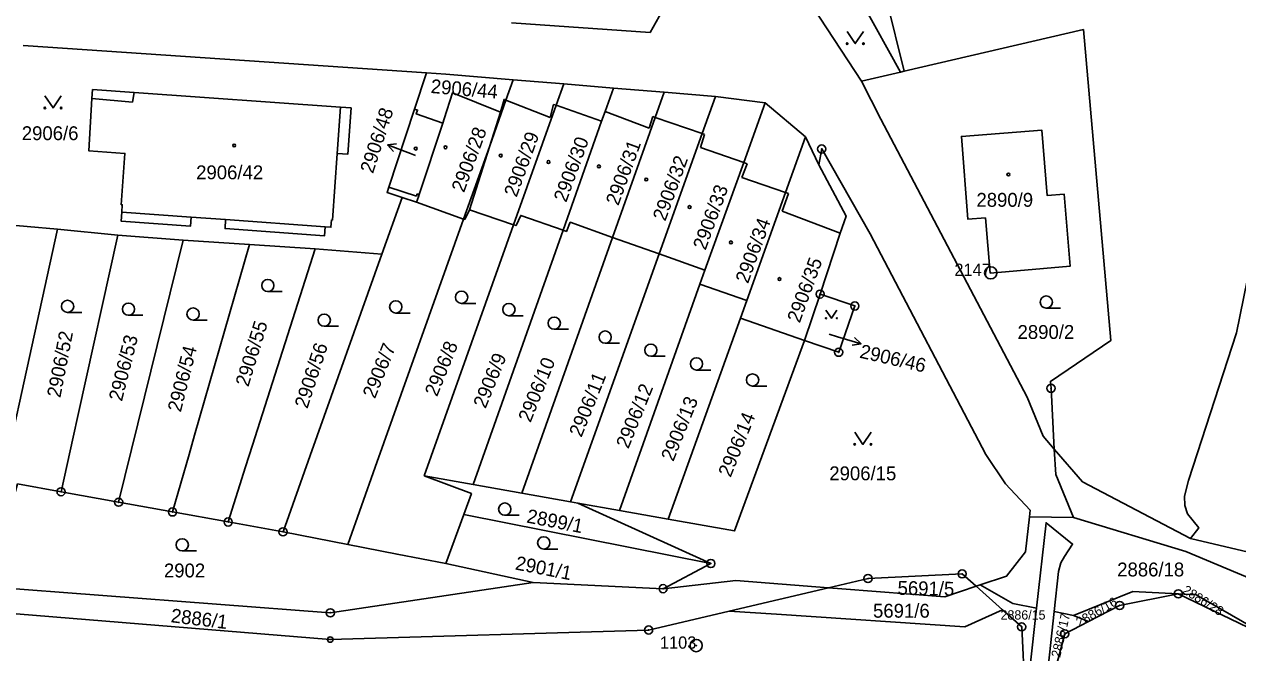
# Model space of a CAD drawing. Extents: x -644096 to -634268, y -1141430 to -1133463.
# Drawn here: x -640028.5 to -639879.7, y -1138359.5 to -1138282.4 of the extents above; entities that cross this region are included whole.
import ezdxf

# ---------------------------------------------------------------- set-up
doc = ezdxf.new("R2010")
doc.units = 0
for name, color, linetype in [('_CIVIL_CONSTRUCTION', 7, 'Continuous'), ('M_Svah_Nasyp', 7, 'Continuous'), ('M_Svah_Zarez', 7, 'Continuous'), ('spodek_zarez', 7, 'Continuous'), ('svrsek_osa_sjezdy', 7, 'Continuous'), ('svrsek_osa_VRT', 7, 'Continuous'), ('svrsek_popisy_VRT', 7, 'Continuous'), ('terminal_VRT', 7, 'Continuous')]:
    doc.layers.add(name, color=color, linetype=linetype)

msp = doc.modelspace()

# ---------------------------------------------------------------- linework, layer by layer
at = {"layer": '_CIVIL_CONSTRUCTION'}
for centre, radius in [((-639930.73, -1138297.73), 0.5), ((-639930.73, -1138297.73), 0.0303), ((-639910.01, -1138312.92), 0.75), ((-639910.01, -1138312.92), 0.03), ((-639930.93, -1138315.53), 0.5), ((-639930.93, -1138315.53), 0.0303), ((-639926.67, -1138316.98), 0.5), ((-639926.67, -1138316.98), 0.0303), ((-639928.65, -1138322.66), 0.5), ((-639928.65, -1138322.66), 0.0303), ((-639902.61, -1138327.08), 0.5), ((-639902.61, -1138327.08), 0.0303), ((-640024, -1138339.77), 0.5), ((-640024, -1138339.77), 0.0303), ((-640016.94, -1138341.05), 0.5), ((-640016.94, -1138341.05), 0.0303), ((-640010.34, -1138342.24), 0.5), ((-640010.34, -1138342.24), 0.0303), ((-640003.51, -1138343.47), 0.5), ((-640003.51, -1138343.47), 0.0303), ((-639996.78, -1138344.68), 0.5), ((-639996.78, -1138344.68), 0.0303), ((-639944.33, -1138348.56), 0.5), ((-639944.33, -1138348.56), 0.0303), ((-639913.51, -1138349.84), 0.5), ((-639950.18, -1138351.66), 0.5), ((-639925.05, -1138350.41), 0.5), ((-639925.05, -1138350.41), 0.0303), ((-639913.51, -1138349.84), 0.0303), ((-639950.18, -1138351.66), 0.0303), ((-639887.01, -1138352.29), 0.5), ((-639887.01, -1138352.29), 0.0303), ((-639990.99, -1138354.61), 0.5), ((-639894.2, -1138353.71), 0.5), ((-639894.2, -1138353.71), 0.0303), ((-639990.99, -1138354.61), 0.0303), ((-639951.96, -1138356.72), 0.5), ((-639951.96, -1138356.72), 0.0303), ((-639906.21, -1138356.34), 0.5), ((-639906.21, -1138356.34), 0.0303), ((-639900.93, -1138357.19), 0.5), ((-639900.93, -1138357.19), 0.0303), ((-639991, -1138357.89), 0.335), ((-639991, -1138357.89), 0.0203), ((-639946.12, -1138358.63), 0.75), ((-639946.12, -1138358.63), 0.03)]:
    msp.add_circle(centre, radius, dxfattribs=at)
at = {"layer": 'M_Svah_Nasyp'}
for p, q in [((-640015.24, -1138291.99), (-640020.21, -1138291.55)), ((-640015.24, -1138291.99), (-640015.04, -1138290.8)), ((-639964.01, -1138293.86), (-639969.45, -1138291.75)), ((-639990.14, -1138298.27), (-639989.73, -1138292.59)), ((-639971.48, -1138297.47), (-639970.13, -1138293.22)), ((-639963.64, -1138292.26), (-639964.01, -1138293.86)), ((-639963.31, -1138292.38), (-639963.64, -1138292.26)), ((-639957.72, -1138294.34), (-639963.31, -1138292.38)), ((-639957.29, -1138293.13), (-639951.87, -1138295.19)), ((-639951.44, -1138293.77), (-639951.87, -1138295.19)), ((-639951.14, -1138293.87), (-639951.44, -1138293.77)), ((-639945.37, -1138295.85), (-639951.14, -1138293.87)), ((-639945.59, -1138297.55), (-639945.09, -1138295.95)), ((-639945.09, -1138295.95), (-639945.37, -1138295.85)), ((-639971.48, -1138297.47), (-639973.94, -1138305.19)), ((-639940.29, -1138299.41), (-639945.59, -1138297.55)), ((-639940.52, -1138301.24), (-639939.88, -1138299.55)), ((-639939.88, -1138299.55), (-639940.29, -1138299.41)), ((-639935.17, -1138303.08), (-639940.52, -1138301.24)), ((-639983.81, -1138302.4), (-639980.43, -1138303.51)), ((-639980.43, -1138303.51), (-639980.33, -1138303.25)), ((-639980.33, -1138303.25), (-639980.08, -1138303.33)), ((-639935.58, -1138305.35), (-639934.8, -1138303.21)), ((-639934.8, -1138303.21), (-639935.17, -1138303.08)), ((-640008.05, -1138306.09), (-640016.56, -1138305.48)), ((-639991.62, -1138307.28), (-640003.82, -1138306.4)), ((-639928.45, -1138308.06), (-639935.58, -1138305.35))]:
    msp.add_line(p, q, dxfattribs=at)
at = {"layer": 'M_Svah_Zarez'}
for centre in [(-640002.77, -1138297.3), (-639980.52, -1138297.69), (-639976.87, -1138297.53), (-639970.09, -1138298.55), (-639964.24, -1138299.33), (-639958.05, -1138299.87), (-639952.24, -1138301.48), (-639907.84, -1138300.87), (-639946.93, -1138304.85), (-639941.86, -1138309.19), (-639935.91, -1138313.68)]:
    msp.add_circle(centre, 0.175, dxfattribs=at)
at = {"layer": 'spodek_zarez'}
msp.add_circle((-638683.07, -1137056.85), 1378.08, dxfattribs=at)
at = {"layer": 'svrsek_osa_sjezdy'}
for p, q in [((-639998.65, -1138315.23), (-639996.9, -1138315.23)), ((-639974.89, -1138316.67), (-639973.14, -1138316.67)), ((-640023.2, -1138317.78), (-640021.45, -1138317.78)), ((-640015.74, -1138318.13), (-640013.99, -1138318.13)), ((-639982.96, -1138317.85), (-639981.21, -1138317.85)), ((-639969.09, -1138318.18), (-639967.34, -1138318.18)), ((-639903.19, -1138317.25), (-639901.44, -1138317.25)), ((-640007.82, -1138318.72), (-640006.07, -1138318.72)), ((-639991.73, -1138319.48), (-639989.98, -1138319.48)), ((-639963.53, -1138319.84), (-639961.78, -1138319.84)), ((-639957.28, -1138321.55), (-639955.53, -1138321.55)), ((-639951.68, -1138323.16), (-639949.93, -1138323.16)), ((-639946.09, -1138324.84), (-639944.34, -1138324.84)), ((-639939.21, -1138326.81), (-639937.46, -1138326.81)), ((-639969.6, -1138342.64), (-639967.85, -1138342.64)), ((-639964.82, -1138346.79), (-639963.07, -1138346.79)), ((-640009.14, -1138347.03), (-640007.39, -1138347.03))]:
    msp.add_line(p, q, dxfattribs=at)
for points in [[(-639927.61, -1138283.31), (-639926.61, -1138284.81), (-639925.61, -1138283.31)], [(-640025.99, -1138291.2), (-640024.99, -1138292.7), (-640023.99, -1138291.2)], [(-639930.21, -1138317.48), (-639929.54, -1138318.49), (-639928.87, -1138317.48)], [(-639926.68, -1138332.46), (-639925.68, -1138333.96), (-639924.68, -1138332.46)]]:
    msp.add_lwpolyline(points, dxfattribs=at)
for centre, radius in [((-639927.61, -1138284.81), 0.1), ((-639925.61, -1138284.81), 0.1), ((-640025.99, -1138292.7), 0.1), ((-640023.99, -1138292.7), 0.1), ((-639998.65, -1138314.48), 0.75), ((-639974.89, -1138315.92), 0.75), ((-640023.2, -1138317.03), 0.75), ((-640015.74, -1138317.38), 0.75), ((-639982.96, -1138317.1), 0.75), ((-639969.09, -1138317.43), 0.75), ((-639903.19, -1138316.5), 0.75), ((-640007.82, -1138317.97), 0.75), ((-639991.73, -1138318.73), 0.75), ((-639963.53, -1138319.09), 0.75), ((-639930.21, -1138318.49), 0.067), ((-639928.87, -1138318.49), 0.067), ((-639957.28, -1138320.8), 0.75), ((-639951.68, -1138322.41), 0.75), ((-639946.09, -1138324.09), 0.75), ((-639939.21, -1138326.06), 0.75), ((-639926.68, -1138333.96), 0.1), ((-639924.68, -1138333.96), 0.1), ((-639969.6, -1138341.89), 0.75), ((-639964.82, -1138346.04), 0.75), ((-640009.14, -1138346.28), 0.75)]:
    msp.add_circle(centre, radius, dxfattribs=at)
at = {"layer": 'svrsek_popisy_VRT'}
for p, q in [((-639983.97, -1138297.21), (-639982.86, -1138297.1)), ((-639981.17, -1138298.28), (-639983.97, -1138297.21)), ((-639983.97, -1138297.21), (-639983.22, -1138298.03)), ((-639980.54, -1138298.52), (-639981.17, -1138298.28)), ((-639929.82, -1138320.43), (-639928.78, -1138320.75)), ((-639928.78, -1138320.75), (-639925.91, -1138321.63)), ((-639925.91, -1138321.63), (-639926.72, -1138320.86)), ((-639925.91, -1138321.63), (-639927.01, -1138321.81))]:
    msp.add_line(p, q, dxfattribs=at)
at = {"layer": 'terminal_VRT'}
for p, q in [((-639937.78, -1138271.21), (-639925.86, -1138289.42)), ((-639979.21, -1138288.39), (-640028.65, -1138285.04)), ((-639980.67, -1138292.84), (-639979.21, -1138288.39)), ((-639921.06, -1138288.3), (-639925.86, -1138289.42)), ((-639921.06, -1138288.3), (-639920.64, -1138288.21)), ((-639968.55, -1138289.24), (-639969.45, -1138291.75)), ((-639962.37, -1138289.75), (-639968.55, -1138289.24)), ((-639956.28, -1138290.26), (-639962.37, -1138289.75)), ((-639950.04, -1138290.77), (-639956.28, -1138290.26)), ((-639943.74, -1138291.3), (-639950.04, -1138290.77)), ((-639937.67, -1138292.09), (-639943.74, -1138291.3)), ((-639932.71, -1138296.24), (-639937.67, -1138292.09)), ((-639931.08, -1138299.69), (-639932.71, -1138296.24)), ((-639984.67, -1138310.64), (-639982.19, -1138303.67)), ((-639980.4, -1138304.27), (-639982.19, -1138303.67)), ((-639974.64, -1138306.33), (-639980.4, -1138304.27)), ((-640032.63, -1138306.87), (-640024.43, -1138307.56)), ((-640024.43, -1138307.56), (-640017.05, -1138308.31)), ((-639979.48, -1138337.8), (-639968.52, -1138307.02)), ((-639973.48, -1138338.87), (-639962.45, -1138307.69)), ((-640017.05, -1138308.31), (-640009.02, -1138308.92)), ((-640016.94, -1138341.05), (-640009.02, -1138308.92)), ((-640009.02, -1138308.92), (-640000.89, -1138309.44)), ((-640000.89, -1138309.44), (-639992.84, -1138309.96)), ((-639967.51, -1138339.93), (-639956.37, -1138308.57)), ((-639950.65, -1138310.6), (-639956.37, -1138308.57)), ((-639992.84, -1138309.96), (-639984.67, -1138310.64)), ((-639961.53, -1138340.99), (-639950.65, -1138310.6)), ((-639945.07, -1138312.58), (-639950.65, -1138310.6)), ((-639945.69, -1138314.31), (-639945.07, -1138312.58)), ((-639955.54, -1138342.06), (-639945.69, -1138314.31)), ((-639939.92, -1138316.33), (-639945.69, -1138314.31)), ((-639932.86, -1138321.2), (-639930.93, -1138315.53)), ((-639940.69, -1138318.48), (-639939.92, -1138316.33)), ((-639949.54, -1138343.13), (-639940.69, -1138318.48)), ((-639932.86, -1138321.2), (-639940.69, -1138318.48)), ((-639973.48, -1138338.87), (-639979.48, -1138337.8)), ((-639967.51, -1138339.93), (-639973.48, -1138338.87)), ((-640016.94, -1138341.05), (-640024, -1138339.77)), ((-639961.53, -1138340.99), (-639967.51, -1138339.93)), ((-640010.34, -1138342.24), (-640016.94, -1138341.05)), ((-640003.51, -1138343.47), (-640010.34, -1138342.24)), ((-639960.65, -1138341.15), (-639961.53, -1138340.99)), ((-639944.33, -1138348.56), (-639960.65, -1138341.15)), ((-639960.65, -1138341.15), (-639955.54, -1138342.06)), ((-639955.54, -1138342.06), (-639949.54, -1138343.13)), ((-639996.78, -1138344.68), (-640003.51, -1138343.47)), ((-639974.61, -1138342.54), (-639976.82, -1138348.57)), ((-639974.61, -1138342.54), (-639944.33, -1138348.56)), ((-639905.27, -1138342.83), (-639899.84, -1138342.91)), ((-639988.82, -1138346.25), (-639996.78, -1138344.68)), ((-639885.53, -1138345.48), (-639875.02, -1138347.98)), ((-639976.82, -1138348.57), (-639966.11, -1138350.91)), ((-639950.18, -1138351.66), (-639944.33, -1138348.56)), ((-639950.18, -1138351.66), (-639966.11, -1138350.91)), ((-639911.8, -1138351.36), (-639911.31, -1138351.2)), ((-639942.08, -1138354.4), (-639929.89, -1138351.54)), ((-639908.57, -1138354.24), (-639911.8, -1138351.36)), ((-639887.01, -1138352.29), (-639874.8, -1138358.19)), ((-639899.86, -1138354.95), (-639902.22, -1138354.47)), ((-639899.86, -1138354.95), (-639898, -1138355.67))]:
    msp.add_line(p, q, dxfattribs=at)
for points in [[(-639968.76, -1138282.27), (-639951.78, -1138283.45), (-639945.53, -1138272.31), (-639954.38, -1138257.06)], [(-639927.88, -1138269.33), (-639925.7, -1138279.99), (-639921.06, -1138288.3)], [(-639920.64, -1138288.21), (-639922.77, -1138279.39), (-639923.21, -1138275.47)], [(-639920.64, -1138288.21), (-639898.65, -1138283.1), (-639895.28, -1138321.22), (-639902.68, -1138326.23), (-639902.61, -1138327.08), (-639902.21, -1138334.54)], [(-639885.53, -1138345.48), (-639884.5, -1138344.2), (-639885.86, -1138342.47), (-639886.21, -1138341.46), (-639886.26, -1138340.32), (-639885.76, -1138338.38), (-639879.87, -1138320.28), (-639872.27, -1138282.97)], [(-639968.55, -1138289.24), (-639976.81, -1138288.55), (-639979.21, -1138288.39)], [(-639968.52, -1138307.02), (-639963.31, -1138292.38), (-639962.37, -1138289.75)], [(-639962.45, -1138307.69), (-639957.72, -1138294.34), (-639957.29, -1138293.13), (-639956.28, -1138290.26)], [(-639925.86, -1138289.42), (-639923.47, -1138294.06), (-639905.52, -1138328.16), (-639903.59, -1138332.94), (-639902.21, -1138334.54)], [(-639988.43, -1138292.68), (-639988.84, -1138298.37), (-639990.14, -1138298.27), (-639990.73, -1138306.45), (-639990.85, -1138306.44), (-639990.92, -1138307.33), (-639991.62, -1138307.28), (-639991.7, -1138308.37), (-640003.9, -1138307.49), (-640003.82, -1138306.4), (-640008.05, -1138306.09), (-640008.13, -1138307.19), (-640016.64, -1138306.57), (-640016.56, -1138305.48), (-640016.5, -1138304.58), (-640016.63, -1138304.57), (-640016.17, -1138298.28), (-640020.61, -1138297.96), (-640020.21, -1138291.55), (-640020.14, -1138290.44), (-640015.04, -1138290.8), (-639989.73, -1138292.59), (-639988.43, -1138292.68)], [(-639969.45, -1138291.75), (-639969.68, -1138291.66), (-639970.13, -1138293.22), (-639976, -1138290.84), (-639977.04, -1138294.03), (-639977.21, -1138294.55)], [(-639974.64, -1138306.33), (-639971.48, -1138297.47), (-639969.45, -1138291.75)], [(-639956.37, -1138308.57), (-639951.14, -1138293.87), (-639950.04, -1138290.77)], [(-639950.65, -1138310.6), (-639945.37, -1138295.85), (-639943.74, -1138291.3)], [(-639982.19, -1138303.67), (-639984.02, -1138303.07), (-639983.81, -1138302.4), (-639980.67, -1138292.84)], [(-639980.67, -1138292.84), (-639980.29, -1138292.97), (-639980.44, -1138293.43), (-639977.21, -1138294.55)], [(-639945.07, -1138312.58), (-639940.29, -1138299.41), (-639937.67, -1138292.09)], [(-639977.21, -1138294.55), (-639980.08, -1138303.33), (-639980.17, -1138303.59), (-639980.4, -1138304.27)], [(-639910.66, -1138306.17), (-639912.83, -1138306.32), (-639913.61, -1138296.19), (-639903.72, -1138295.43), (-639903.1, -1138303.42), (-639901.02, -1138303.26), (-639900.26, -1138312.1), (-639910.06, -1138312.96), (-639910.66, -1138306.17)], [(-639939.92, -1138316.33), (-639935.17, -1138303.08), (-639932.71, -1138296.24)], [(-639905.27, -1138342.83), (-639905.18, -1138342.03), (-639908.18, -1138338.79), (-639910.59, -1138335.19), (-639924.77, -1138308.15), (-639930.73, -1138297.73), (-639931.08, -1138299.69)], [(-639931.08, -1138299.69), (-639927.74, -1138305.98), (-639928.45, -1138308.06), (-639930.93, -1138315.53)], [(-639988.82, -1138346.25), (-639985.48, -1138336.74), (-639974.64, -1138306.33)], [(-639968.52, -1138307.02), (-639973.94, -1138305.19), (-639974.5, -1138306.38), (-639974.64, -1138306.33)], [(-639962.45, -1138307.69), (-639967.64, -1138305.88), (-639968.2, -1138307.13), (-639968.52, -1138307.02)], [(-640031.21, -1138338.46), (-640030, -1138332.96), (-640029.14, -1138329.03), (-640024.43, -1138307.56)], [(-639956.37, -1138308.57), (-639961.57, -1138306.72), (-639962.03, -1138307.84), (-639962.45, -1138307.69)], [(-640024, -1138339.77), (-640022.52, -1138333.06), (-640021.91, -1138330.3), (-640017.05, -1138308.31)], [(-640010.34, -1138342.24), (-640008.31, -1138335.2), (-640007.63, -1138332.82), (-640000.89, -1138309.44)], [(-640003.51, -1138343.47), (-640001.37, -1138336.73), (-640000.52, -1138334.07), (-639992.84, -1138309.96)], [(-639984.67, -1138310.64), (-639993.45, -1138335.32), (-639996.78, -1138344.68)], [(-639930.93, -1138315.53), (-639926.67, -1138316.98), (-639928.65, -1138322.66), (-639932.86, -1138321.2)], [(-639949.54, -1138343.13), (-639941.42, -1138344.57), (-639932.86, -1138321.2)], [(-639902.21, -1138334.54), (-639898.74, -1138338.57), (-639885.53, -1138345.48)], [(-639899.84, -1138342.91), (-639902.04, -1138337.66), (-639902.21, -1138334.54)], [(-639979.48, -1138337.8), (-639973.68, -1138340), (-639974.61, -1138342.54)], [(-640024, -1138339.77), (-640029.34, -1138338.81), (-640032.65, -1138350.73)], [(-639911.31, -1138351.2), (-639908.07, -1138350.13), (-639905.74, -1138347.12), (-639905.27, -1138342.83)], [(-639902.22, -1138354.47), (-639901.68, -1138349.54), (-639901.4, -1138348.48), (-639900.97, -1138347.7), (-639899.96, -1138346.18), (-639903.22, -1138343.57), (-639904.38, -1138354.04)], [(-639899.84, -1138342.91), (-639886.09, -1138347.1), (-639872.94, -1138352.6), (-639845.94, -1138357.86)], [(-639976.82, -1138348.57), (-639982.81, -1138347.43), (-639988.82, -1138346.25)], [(-639966.11, -1138350.91), (-639990.99, -1138354.61), (-640032.85, -1138351.44)], [(-639929.89, -1138351.54), (-639941.26, -1138350.67), (-639950.18, -1138351.66)], [(-639929.89, -1138351.54), (-639925.05, -1138350.41), (-639913.51, -1138349.84), (-639911.8, -1138351.36)], [(-639904.38, -1138354.04), (-639907.29, -1138353.45), (-639911.31, -1138351.2)], [(-639929.89, -1138351.54), (-639928.27, -1138351.67), (-639915.65, -1138352.64), (-639911.8, -1138351.36)], [(-639887.01, -1138352.29), (-639892.6, -1138351.98), (-639899.86, -1138354.95)], [(-639898, -1138355.67), (-639894.2, -1138353.71), (-639887.01, -1138352.29)], [(-639887.01, -1138352.29), (-639884.83, -1138352.4), (-639874.8, -1138358.19)], [(-639908.57, -1138354.24), (-639913.2, -1138356.32), (-639936.27, -1138354.79), (-639942.08, -1138354.4)], [(-639905.83, -1138364.11), (-639906.21, -1138356.34), (-639908.57, -1138354.24)], [(-639904.38, -1138354.04), (-639905.5, -1138364.15), (-639905.83, -1138364.11)], [(-640033.56, -1138354.39), (-639991, -1138357.89), (-639951.96, -1138356.72), (-639942.08, -1138354.4)], [(-639902.84, -1138364.38), (-639903.08, -1138362.43), (-639902.22, -1138354.47)], [(-639902.84, -1138364.38), (-639900.93, -1138357.19), (-639898, -1138355.67)]]:
    msp.add_lwpolyline(points, dxfattribs=at)

# ---------------------------------------------------------------- texts
at = {"layer": '_CIVIL_CONSTRUCTION'}
for s, p in [('2147', (-639914.46, -1138313.29)), ('1103', (-639950.57, -1138359.01))]:
    msp.add_text(s, height=1.5, dxfattribs=at).set_placement(p)
at = {"layer": 'svrsek_osa_VRT'}
for s, height, rotation, p in [('2906/44', 1.7, 355, (-639978.72, -1138290.86)), ('2906/48', 1.7, 72, (-639985.76, -1138300.83)), ('2906/28', 1.7, 70, (-639974.59, -1138303.16)), ('2906/29', 1.7, 70, (-639968.15, -1138303.74)), ('2906/30', 1.7, 70, (-639962.06, -1138304.36)), ('2906/31', 1.7, 70, (-639955.67, -1138304.77)), ('2906/32', 1.7, 70, (-639949.91, -1138306.67)), ('2906/33', 1.7, 70, (-639944.98, -1138310.23)), ('2906/34', 1.7, 70, (-639939.77, -1138314.32)), ('2906/35', 1.7, 70, (-639933.43, -1138319.16)), ('2906/55', 1.7, 73, (-640001.04, -1138326.98)), ('2906/52', 1.7, 79, (-640024.09, -1138328.31)), ('2906/53', 1.7, 76, (-640016.54, -1138328.76)), ('2906/7', 1.7, 68, (-639985.52, -1138328.44)), ('2906/8', 1.7, 68, (-639977.9, -1138328.19)), ('2906/54', 1.7, 76, (-640009.32, -1138330.09)), ('2906/56', 1.7, 72, (-639993.8, -1138329.66)), ('2906/9', 1.7, 68, (-639971.95, -1138329.65)), ('2906/46', 1.7, 347, (-639926.18, -1138323.31)), ('2906/10', 1.7, 68, (-639966.44, -1138331.36)), ('2906/11', 1.7, 68, (-639960.2, -1138333.17)), ('2906/12', 1.7, 68, (-639954.44, -1138334.58)), ('2906/13', 1.7, 68, (-639948.93, -1138336.14)), ('2906/14', 1.7, 68, (-639941.91, -1138338.09)), ('2899/1', 1.7, 349, (-639967.01, -1138343.53)), ('2901/1', 1.7, 349, (-639968.4, -1138349.29)), ('5691/5', 1.7, 359, (-639921.44, -1138352.4)), ('2886/16', 1.14, 30, (-639899.14, -1138356.36)), ('2886/28', 1.14, 328, (-639886.59, -1138352.12)), ('2886/1', 1.7, 353, (-640010.61, -1138355.76)), ('2886/17', 1.14, 77, (-639901.5, -1138360.17))]:
    msp.add_text(s, height=height, rotation=rotation, dxfattribs=at).set_placement(p)
for s, height, p in [('2906/6', 1.7, (-640028.82, -1138296.65)), ('2906/42', 1.7, (-640007.44, -1138301.45)), ('2890/9', 1.7, (-639911.76, -1138304.82)), ('2890/2', 1.7, (-639906.72, -1138321.03)), ('2906/15', 1.7, (-639929.8, -1138338.36)), ('2902', 1.7, (-640011.39, -1138350.27)), ('2886/18', 1.7, (-639894.5, -1138350.15)), ('5691/6', 1.7, (-639924.44, -1138355.21)), ('2886/15', 1.14, (-639908.8, -1138355.44))]:
    msp.add_text(s, height=height, dxfattribs=at).set_placement(p)

doc.saveas('drawing.dxf')
